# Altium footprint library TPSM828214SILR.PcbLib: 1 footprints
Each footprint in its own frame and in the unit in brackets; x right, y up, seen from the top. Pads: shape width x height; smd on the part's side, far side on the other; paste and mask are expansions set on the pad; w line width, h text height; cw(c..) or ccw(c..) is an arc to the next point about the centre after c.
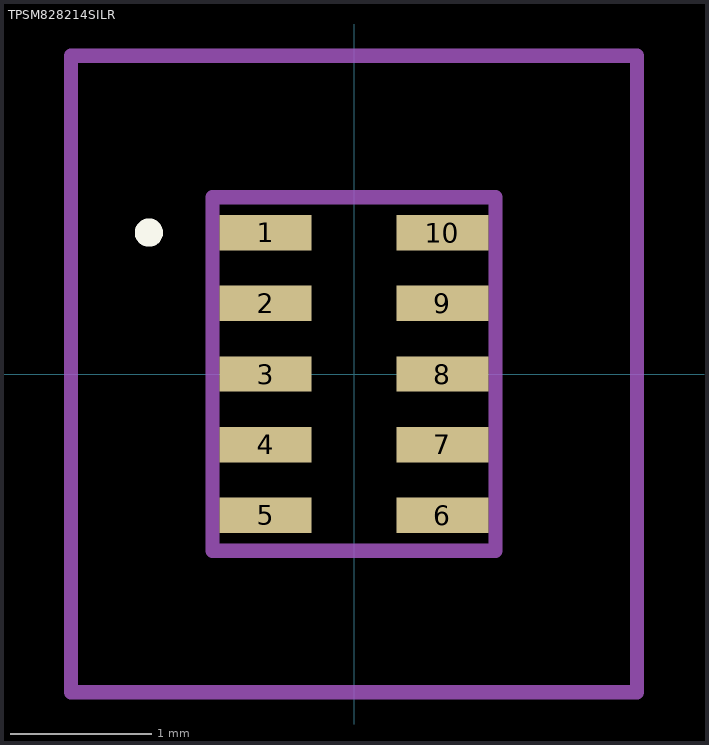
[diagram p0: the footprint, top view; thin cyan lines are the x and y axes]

## TPSM828214SILR [mm]
pads (10):
  rect 0.65x0.25 smd: 1(-0.625,1) 2(-0.625,0.5) 3(-0.625,0) 4(-0.625,-0.5) 5(-0.625,-1) 6(0.625,-1) 7(0.625,-0.5) 8(0.625,0) 9(0.625,0.5) 10(0.625,1)
Top Overlay:
  lines w0.1: -1.5,1 cw(c-1.45,1) -1.4,1 ; -1.5,1 -1.5,1 ; -1.5,1 ccw(c-1.45,1) -1.4,1 ; -1.4,1 -1.4,1
Mechanical 15:
  lines w0.1: -1,-1.25 1,-1.25 1,1.25 -1,1.25 -1,-1.25
Mechanical 20:
  lines w0.1: -2,-2.25 2,-2.25 2,2.25 -2,2.25 -2,-2.25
